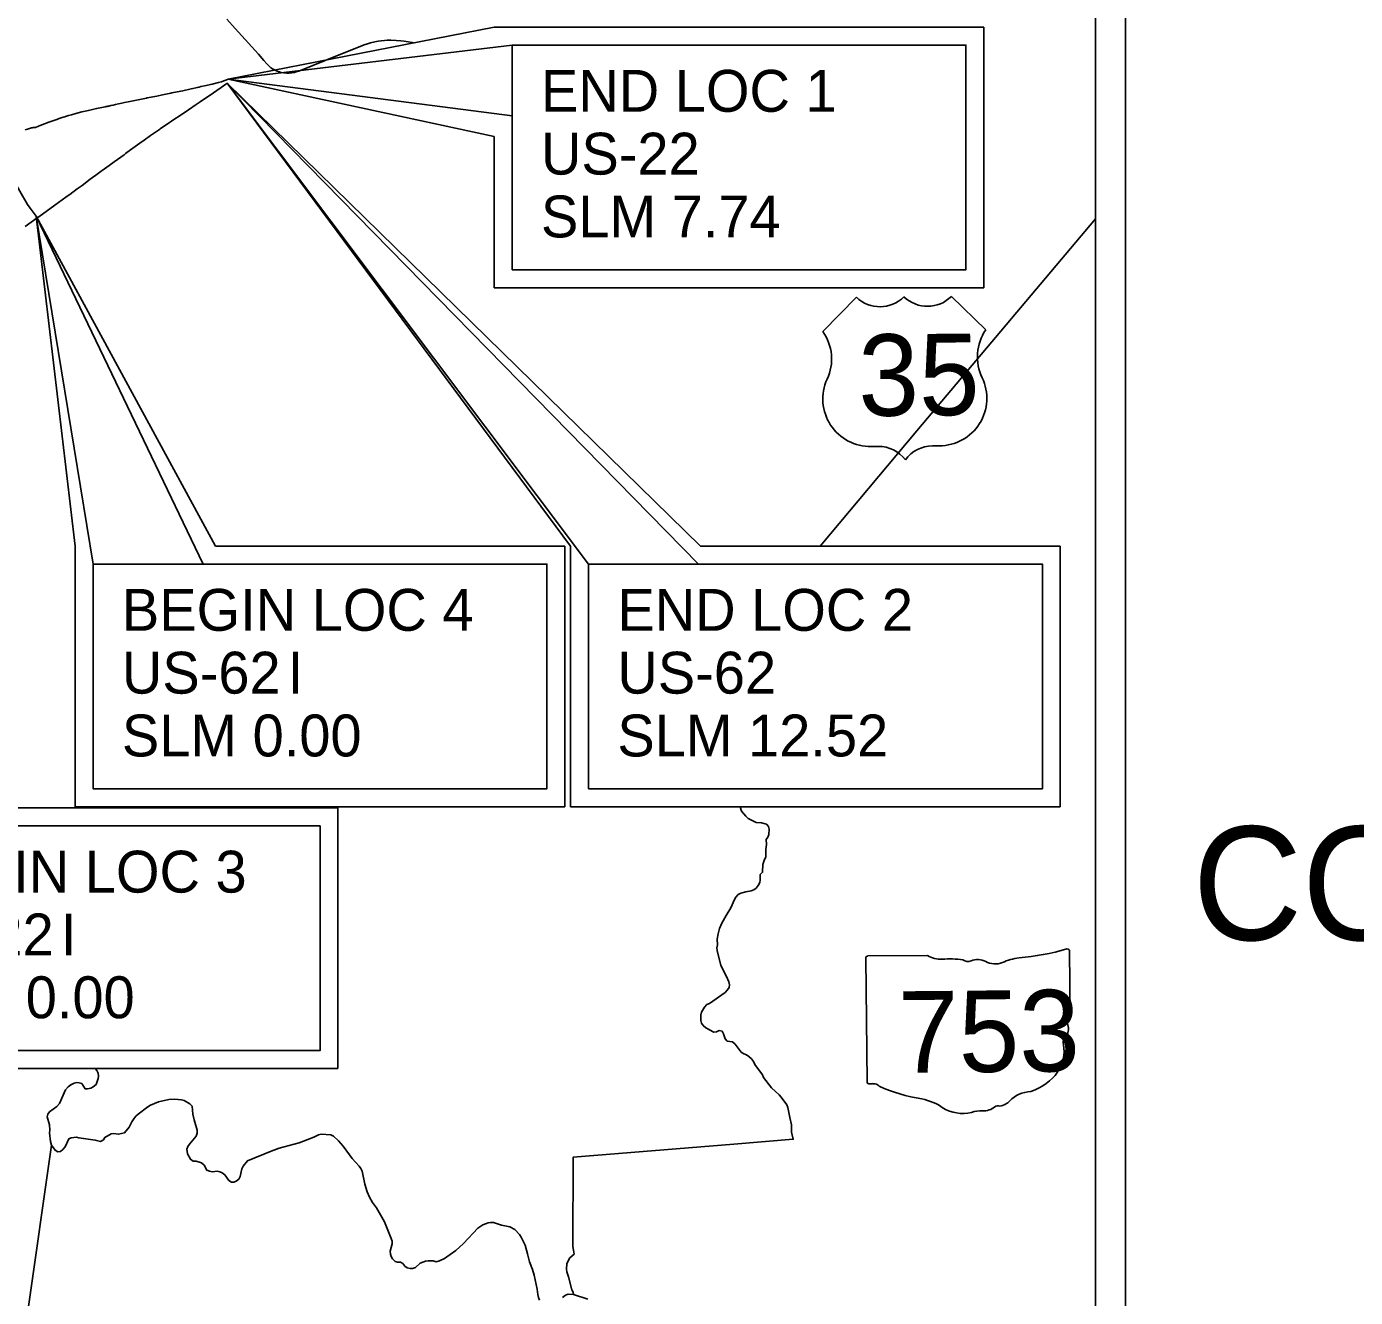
# Model space of a CAD drawing. Extents: x -12 to 164, y -741 to 24.
# Drawn here: x 8.492 to 12.934, y 14.264 to 18.513 of the extents above; entities that cross this region are included whole.
import ezdxf

# ---------------------------------------------------------------- set-up
doc = ezdxf.new("R2010")
doc.units = 0
for name, color, linetype in [('Default', 7, 'Continuous'), ('PM_P_Channelizing_Line', 7, 'Continuous'), ('PM_P_Crosswalk', 7, 'Continuous'), ('PM_P_Parking_Lot_Stall', 7, 'Continuous'), ('PM_P_Stop_Line', 7, 'Continuous'), ('PM_X_Edge_Line', 7, 'Continuous'), ('SC_Scratch1', 7, 'Continuous'), ('SH_Data', 7, 'Continuous'), ('SH_Text', 7, 'Continuous')]:
    doc.layers.add(name, color=color, linetype=linetype)

msp = doc.modelspace()

# ---------------------------------------------------------------- linework, layer by layer
at = {"layer": 'PM_P_Channelizing_Line'}
for points in [[(11.1449, 16.7765), (11.4684, 17.1617), (12.0655, 17.8702)], [(10.3198, 14.2737), (10.3186, 14.2816), (10.3146, 14.29), (10.3037, 14.3337), (10.2981, 14.35), (10.2969, 14.3588), (10.2978, 14.3775), (10.308, 14.3964), (10.3228, 14.4096), (10.3199, 14.4224), (10.3178, 14.4348), (10.3187, 14.7329), (10.8562, 14.7766), (11.0545, 14.7932), (11.0493, 14.8165), (11.0487, 14.8253), (11.049, 14.8416), (11.0428, 14.8664), (11.0363, 14.8999), (11.0332, 14.9084), (11.0148, 14.9339), (11.0076, 14.9417), (10.9816, 14.9647), (10.9554, 15.0002), (10.9523, 15.0081), (10.9264, 15.043), (10.922, 15.0527), (10.9148, 15.0622), (10.9064, 15.0703), (10.8982, 15.0757), (10.8891, 15.0789), (10.8807, 15.0845), (10.8601, 15.1109), (10.8516, 15.1188), (10.8341, 15.1211), (10.8269, 15.1289), (10.8213, 15.1456), (10.8169, 15.1547), (10.8069, 15.1569), (10.7978, 15.1525), (10.7896, 15.1516), (10.7627, 15.1658), (10.7539, 15.1737), (10.7486, 15.1815), (10.7455, 15.1906), (10.7456, 15.2079), (10.7484, 15.2179), (10.7579, 15.2351), (10.7661, 15.2436), (10.7745, 15.2476), (10.8267, 15.2842), (10.8355, 15.2923), (10.84, 15.3004), (10.8412, 15.3098), (10.8397, 15.3192), (10.8316, 15.3375), (10.8126, 15.3742), (10.7999, 15.4247), (10.799, 15.4332), (10.8015, 15.4429), (10.8006, 15.4621), (10.8038, 15.4806), (10.8083, 15.4978), (10.8155, 15.5156), (10.83, 15.5416), (10.8464, 15.567), (10.8581, 15.5945), (10.8632, 15.6027), (10.871, 15.6111), (10.8795, 15.6164), (10.8965, 15.6204), (10.914, 15.6238), (10.9228, 15.6276), (10.931, 15.6329), (10.9379, 15.642), (10.9427, 15.652), (10.9446, 15.6601), (10.944, 15.6783), (10.9522, 15.6861), (10.9535, 15.7118), (10.9586, 15.7285), (10.9633, 15.7366), (10.9631, 15.7623), (10.965, 15.7792), (10.9644, 15.7949), (10.9701, 15.8037), (10.9733, 15.8118), (10.9743, 15.83), (10.9724, 15.8385), (10.9652, 15.8463), (10.9489, 15.8508), (10.9307, 15.8518), (10.9038, 15.8657), (10.8957, 15.8732), (10.8819, 15.8902), (10.8771, 15.9051)], [(8.7216, 15.0297), (8.7269, 15.023), (8.731, 15.0145), (8.7325, 15.0041), (8.7316, 14.996), (8.724, 14.9766), (8.7139, 14.9687), (8.7061, 14.9644), (8.6954, 14.9616), (8.6875, 14.9622), (8.676, 14.9798), (8.6672, 14.9821), (8.6594, 14.983), (8.6509, 14.9806), (8.6396, 14.9749), (8.6305, 14.9681), (8.622, 14.959), (8.6018, 14.9133), (8.5929, 14.9033), (8.5681, 14.8848), (8.5624, 14.8767), (8.5608, 14.8682), (8.568, 14.8416), (8.5692, 14.8237), (8.5685, 14.8149), (8.5719, 14.7854), (8.575, 14.7735), (8.4965, 14.2182)], [(8.575, 14.7735), (8.5872, 14.7565), (8.5959, 14.7515), (8.6047, 14.7527), (8.6132, 14.7593), (8.6211, 14.7674), (8.6331, 14.7949), (8.6412, 14.7984), (8.6588, 14.7999), (8.667, 14.7977), (8.7215, 14.7906), (8.7385, 14.7858), (8.7485, 14.7914), (8.7539, 14.7996), (8.7746, 14.8111), (8.7825, 14.8127), (8.7991, 14.8101), (8.8195, 14.8151), (8.8346, 14.8335), (8.8431, 14.851), (8.8504, 14.8617), (8.857, 14.8708), (8.8648, 14.8776), (8.8966, 14.902), (8.906, 14.9073), (8.933, 14.9185), (8.9676, 14.9262), (8.987, 14.9277), (9.0093, 14.9255), (9.0184, 14.9229), (9.0375, 14.9122), (9.0453, 14.904), (9.0474, 14.8777), (9.0518, 14.8579), (9.0623, 14.824), (9.062, 14.8134), (9.0588, 14.804), (9.0361, 14.7767), (9.0308, 14.7686), (9.0279, 14.7598), (9.0301, 14.7441), (9.0401, 14.7265), (9.0485, 14.7202), (9.0585, 14.7196), (9.0767, 14.7142), (9.0849, 14.7066), (9.0945, 14.6897), (9.1033, 14.6865), (9.1127, 14.6849), (9.1212, 14.6855), (9.129, 14.6861), (9.1378, 14.6845), (9.146, 14.6814), (9.1547, 14.6741), (9.1678, 14.6556), (9.1763, 14.6499), (9.1841, 14.6502), (9.1929, 14.6533), (9.2008, 14.6602), (9.2058, 14.6686), (9.2119, 14.694), (9.216, 14.7031), (9.2298, 14.7212), (9.3096, 14.7539), (9.3357, 14.7632), (9.4029, 14.7812), (9.4519, 14.8002), (9.4682, 14.808), (9.4761, 14.8102), (9.509, 14.8075), (9.5174, 14.8038), (9.535, 14.7883), (9.55, 14.7707), (9.5803, 14.7292), (9.604, 14.7034), (9.6097, 14.695), (9.6131, 14.6871), (9.622, 14.6429), (9.6301, 14.6177), (9.6376, 14.5995), (9.6482, 14.5822), (9.6616, 14.5643), (9.6879, 14.5169), (9.7109, 14.4616), (9.7134, 14.4522), (9.7134, 14.444), (9.7076, 14.4187), (9.7085, 14.4096), (9.711, 14.4014), (9.7154, 14.3932), (9.7238, 14.3847), (9.7323, 14.3822), (9.7414, 14.3819), (9.7495, 14.3781), (9.7558, 14.3693), (9.7646, 14.3639), (9.7736, 14.3614), (9.7824, 14.3617), (9.7919, 14.3648), (9.8079, 14.3791), (9.8252, 14.386), (9.8343, 14.3872), (9.8506, 14.3872), (9.8612, 14.383), (9.8725, 14.3865), (9.8892, 14.3942), (9.9263, 14.4208), (9.9527, 14.4445), (10.0002, 14.4958), (10.0169, 14.5071), (10.0348, 14.5136), (10.043, 14.5148), (10.0524, 14.5145), (10.0793, 14.5065), (10.1069, 14.5008), (10.1238, 14.4914), (10.1401, 14.4753), (10.1454, 14.4662), (10.1582, 14.4389), (10.1659, 14.4106), (10.1727, 14.3836), (10.1833, 14.3579), (10.1892, 14.3394), (10.1985, 14.2926), (10.2006, 14.2741), (10.2034, 14.2647), (10.2069, 14.2552)], [(10.2834, 14.2641), (10.2932, 14.2725), (10.3023, 14.275), (10.3198, 14.2737), (10.3681, 14.2582)]]:
    msp.add_lwpolyline(points, dxfattribs=at)
at = {"layer": 'PM_P_Crosswalk'}
for points in [[(9.0138, 18.299), (9.0416, 18.3052), (9.0626, 18.3099), (9.0682, 18.3111), (9.0741, 18.3125), (9.0865, 18.3153), (9.1124, 18.3213), (9.133, 18.3261), (9.1435, 18.3291), (9.1515, 18.3314), (9.1579, 18.3338), (9.1653, 18.3375)], [(9.0585, 18.2528), (9.0722, 18.262), (9.0798, 18.2672), (9.102, 18.2823), (9.1423, 18.3099), (9.1581, 18.3208), (9.1611, 18.3231), (9.1618, 18.3237)], [(8.7732, 18.2491), (8.7809, 18.2508), (8.7885, 18.2524), (8.799, 18.2547), (8.8097, 18.257), (8.8191, 18.259), (8.8315, 18.2616), (8.8643, 18.2684), (8.8925, 18.2742), (8.8944, 18.2746), (8.927, 18.2812), (8.9463, 18.2852), (8.9745, 18.2909), (8.977, 18.2914), (9.0074, 18.2976), (9.0138, 18.299)], [(8.6003, 18.2056), (8.6146, 18.2103), (8.6199, 18.212), (8.6219, 18.2127), (8.6321, 18.2157), (8.6416, 18.2184), (8.6563, 18.2227), (8.6761, 18.2278), (8.6985, 18.233), (8.726, 18.239), (8.7429, 18.2427), (8.7541, 18.2451)], [(8.7541, 18.2451), (8.7581, 18.2459)], [(8.7581, 18.2459), (8.7615, 18.2466), (8.7632, 18.247), (8.7669, 18.2478)], [(8.7669, 18.2478), (8.7732, 18.2491)], [(8.9694, 18.1924), (8.9764, 18.1972), (8.9809, 18.2002), (9.0084, 18.2187), (9.0331, 18.2355), (9.0585, 18.2528)], [(8.4866, 18.1676), (8.4948, 18.1702), (8.5085, 18.1745), (8.5105, 18.1751), (8.5136, 18.1757), (8.5172, 18.176), (8.522, 18.1763)], [(8.522, 18.1763), (8.5313, 18.1799), (8.5376, 18.1822), (8.5665, 18.1935), (8.5928, 18.2032), (8.6003, 18.2056)], [(8.823, 18.089), (8.8396, 18.1009), (8.8707, 18.1238), (8.8852, 18.1341), (8.9063, 18.1491), (8.9092, 18.1511), (8.9362, 18.1697), (8.9382, 18.171), (8.9694, 18.1924)], [(8.5273, 17.8735), (8.5233, 17.879), (8.5038, 17.906), (8.4952, 17.9188), (8.4855, 17.9339), (8.4777, 17.9471), (8.469, 17.9629), (8.4574, 17.9857), (8.4383, 18.0248), (8.4345, 18.0324), (8.3982, 18.1068), (8.3923, 18.1191), (8.3867, 18.1311), (8.3849, 18.1348), (8.3837, 18.1379)], [(8.7679, 18.0488), (8.7849, 18.0612), (8.8175, 18.0849), (8.823, 18.089)], [(8.7446, 18.0322), (8.7679, 18.0488)], [(8.6234, 17.9431), (8.631, 17.9487), (8.6359, 17.9523), (8.6606, 17.9704), (8.6771, 17.9825), (8.7044, 18.0028)], [(8.7044, 18.0028), (8.7119, 18.0084), (8.7237, 18.017), (8.7414, 18.0299), (8.7446, 18.0322)], [(8.487, 17.8447), (8.5273, 17.8735), (8.5324, 17.8773), (8.5863, 17.9162), (8.6234, 17.9431)]]:
    msp.add_lwpolyline(points, dxfattribs=at)
at = {"layer": 'PM_P_Parking_Lot_Stall'}
for p, q in [((11.9805, 15.2062), (11.9785, 15.4226)), ((11.2977, 15.3988), (11.3015, 14.9853)), ((11.5037, 15.4078), (11.3043, 15.406)), ((11.9805, 15.2063), (11.9805, 15.2062))]:
    msp.add_line(p, q, dxfattribs=at)
for centre, major_axis, start_param, end_param in [((11.7307, 15.9738), (0.7222, 0.0068), 4.814394, 5.042369), ((11.9709, 15.4234), (0.00758, 0.00007), 6.141152, 7.989035), ((11.3054, 15.3997), (0.00789, 0.00007), 1.712693, 3.28349), ((11.5508, 15.4563), (0.0765, 0.0007), 4.042523, 4.731795), ((11.5788, 15.1764), (0.2747, 0.0026), 1.404758, 1.657858), ((11.639, 15.405), (0.0221, 0.0002), 3.836095, 5.185415), ((11.6719, 15.3575), (0.0459, 0.0004), 0.950623, 2.079405), ((11.7305, 15.4236), (0.0552, 0.0005), 4.081561, 5.145723), ((11.8293, 15.2846), (0.1453, 0.0014), 1.699011, 2.107814), ((11.9789, 15.1904), (0.0117, 0.0001), 1.883978, 3.671073), ((11.9725, 15.2053), (0.00811, 0.00008), 5.05454, 6.418171), ((11.9046, 15.1623), (0.0704, 0.0007), 5.934695, 6.695948), ((11.7795, 15.0863), (0.1806, 0.0017), 5.101752, 6.440018), ((12.0086, 15.116), (0.0512, 0.0005), 2.387724, 3.262537), ((11.3094, 14.9845), (0.00796, 0.00007), 3.00124, 4.508301), ((11.3102, 15.0268), (0.0607, 0.0006), 4.665946, 4.897461), ((11.3233, 14.9616), (0.0219, 0.0002), 0.519207, 1.627899), ((11.5963, 15.3358), (0.5215, 0.0049), 4.195997, 4.488961), ((11.4458, 14.8009), (0.1632, 0.0015), 0.823519, 1.323587), ((11.8577, 14.8744), (0.0989, 0.0009), 1.647645, 2.488434), ((11.6208, 14.9624), (0.1035, 0.001), 4.026481, 4.996735), ((11.682, 14.82), (0.0851, 0.0008), 1.495662, 1.94098), ((11.6885, 14.932), (0.0552, 0.0005), 4.691044, 5.507374), ((11.7388, 14.8925), (0.0155, 0.0001), 1.147584, 2.315152), ((11.7316, 14.9492), (0.0584, 0.0005), 4.937069, 5.64225)]:
    msp.add_ellipse(centre, major_axis=major_axis, ratio=0.8, start_param=start_param, end_param=end_param, dxfattribs=at)
at = {"layer": 'PM_P_Stop_Line'}
for p, q in [((11.2658, 17.6084), (11.1534, 17.4939)), ((11.6982, 17.499), (11.5836, 17.6114)), ((11.3159, 17.1094), (11.3386, 17.1096)), ((11.5202, 17.1114), (11.5429, 17.1116))]:
    msp.add_line(p, q, dxfattribs=at)
for centre, radius, start, end in [((11.3445, 17.6902), 0.1135, 226.1115, 314.9656), ((11.5034, 17.6917), 0.1135, 226.1115, 314.9656), ((11.0241, 17.4015), 0.1589, 335.0857, 35.5395), ((11.8292, 17.4091), 0.1589, 145.5376, 205.9914), ((11.3126, 17.2683), 0.1589, 155.3705, 271.1768), ((11.5432, 17.2705), 0.1589, 269.9003, 25.7066), ((11.3397, 16.9961), 0.1135, 37.4084, 90.5385), ((11.5213, 16.9979), 0.1135, 90.5385, 143.6686)]:
    msp.add_arc(centre, radius, start, end, dxfattribs=at)
at = {"layer": 'PM_X_Edge_Line'}
msp.add_lwpolyline([(9.1611, 18.5381), (9.1889, 18.5069), (9.2668, 18.4208), (9.2849, 18.3996), (9.2946, 18.3888), (9.3017, 18.3818), (9.3088, 18.3756), (9.3134, 18.3726), (9.3188, 18.3693), (9.3245, 18.3665), (9.3299, 18.364), (9.3371, 18.3616), (9.3431, 18.3598), (9.3515, 18.3583), (9.3608, 18.3573), (9.3697, 18.3575), (9.3784, 18.3583), (9.387, 18.36), (9.3933, 18.362), (9.4014, 18.3645), (9.5362, 18.4184), (9.6015, 18.4443), (9.6208, 18.452), (9.6314, 18.4557), (9.6418, 18.4587), (9.6557, 18.4621), (9.667, 18.4642), (9.677, 18.4657), (9.6884, 18.4671), (9.6967, 18.4675), (9.71, 18.4678), (9.7275, 18.4672), (9.7427, 18.4659), (9.7537, 18.4645), (9.7671, 18.4623), (9.7803, 18.4597), (9.7841, 18.4587)], dxfattribs=at)
at = {"layer": 'SH_Data'}
for points in [[(6.9766, 21), (2, 21), (2, 8.9058), (12.1655, 8.9058), (12.1655, 18.6562)], [(12.0655, 18.6562), (12.0655, 9.0058), (2.1, 9.0058), (2.1, 20.9), (6.9766, 20.9)]]:
    msp.add_lwpolyline(points, dxfattribs=at)
for points in [[(10.1151, 18.4517), (9.1653, 18.3375), (10.1151, 18.2144)], [(10.1151, 18.4517), (11.6322, 18.4517), (11.6322, 17.7003), (10.1151, 17.7003)], [(10.3705, 16.7165), (9.1618, 18.3237), (10.7381, 16.7165)], [(8.7142, 16.7165), (8.5233, 17.879), (9.0817, 16.7165)], [(8.7142, 16.7165), (10.2312, 16.7165), (10.2312, 15.9651), (8.7142, 15.9651)], [(10.3705, 16.7165), (11.8876, 16.7165), (11.8876, 15.9651), (10.3705, 15.9651)], [(7.9556, 15.8411), (9.4727, 15.8411), (9.4727, 15.0897), (7.9556, 15.0897)]]:
    msp.add_lwpolyline(points, close=True, dxfattribs=at)
at = {"layer": 'SH_Text'}
for p, q in [((10.0551, 18.5117), (9.1653, 18.3375)), ((11.6922, 18.5117), (10.0551, 18.5117)), ((11.6922, 17.6403), (11.6922, 18.5117)), ((10.3105, 16.7765), (9.1618, 18.3237)), ((9.1618, 18.3237), (10.7449, 16.7765)), ((9.1653, 18.3375), (10.0551, 18.1458)), ((10.0551, 18.1458), (10.0551, 17.6403)), ((8.6542, 16.7765), (8.5233, 17.879)), ((8.5233, 17.879), (9.1228, 16.7765)), ((10.0551, 17.6403), (11.6922, 17.6403)), ((8.6542, 15.9051), (8.6542, 16.7765)), ((9.1228, 16.7765), (10.2912, 16.7765)), ((10.2912, 16.7765), (10.2912, 15.9051)), ((10.3105, 15.9051), (10.3105, 16.7765)), ((10.7449, 16.7765), (11.9476, 16.7765)), ((11.9476, 16.7765), (11.9476, 15.9051)), ((10.2912, 15.9051), (8.6542, 15.9051)), ((11.9476, 15.9051), (10.3105, 15.9051)), ((8.3995, 15.9011), (9.5327, 15.9011)), ((9.5327, 15.9011), (9.5327, 15.0297)), ((9.5327, 15.0297), (7.8956, 15.0297))]:
    msp.add_line(p, q, dxfattribs=at)

# ---------------------------------------------------------------- texts
at = {"layer": 'Default'}
for s, p in [('END LOC 1', (10.2114, 18.2285)), ('US-22', (10.2114, 18.0185)), ('SLM 7.74', (10.2114, 17.8085)), ('BEGIN LOC 4', (8.8104, 16.4932)), ('END LOC 2', (10.4668, 16.4932)), ('US-62', (8.8104, 16.2832)), ('I', (9.3648, 16.2832)), ('US-62', (10.4668, 16.2832)), ('SLM 0.00', (8.8104, 16.0732)), ('SLM 12.52', (10.4668, 16.0732)), ('BEGIN LOC 3', (8.0519, 15.6179)), ('US-22', (8.0519, 15.4079)), ('I', (8.6062, 15.4079)), ('SLM 0.00', (8.0519, 15.1979))]:
    msp.add_text(s, height=0.14, dxfattribs=at).set_placement(p)
at = {"layer": 'PM_P_Parking_Lot_Stall'}
msp.add_text('753', height=0.27243, rotation=0.5385, dxfattribs=at).set_placement((11.4061, 15.0154))
at = {"layer": 'PM_P_Stop_Line'}
msp.add_text('35', height=0.27243, rotation=0.5385, dxfattribs=at).set_placement((11.2734, 17.2112))
at = {"layer": 'SC_Scratch1'}
msp.add_text('CONCORD, GREEN, JASPER, AND UNION TOWNSHIPS', height=0.38, dxfattribs=at).set_placement((12.3896, 15.4591))

doc.saveas('drawing.dxf')
